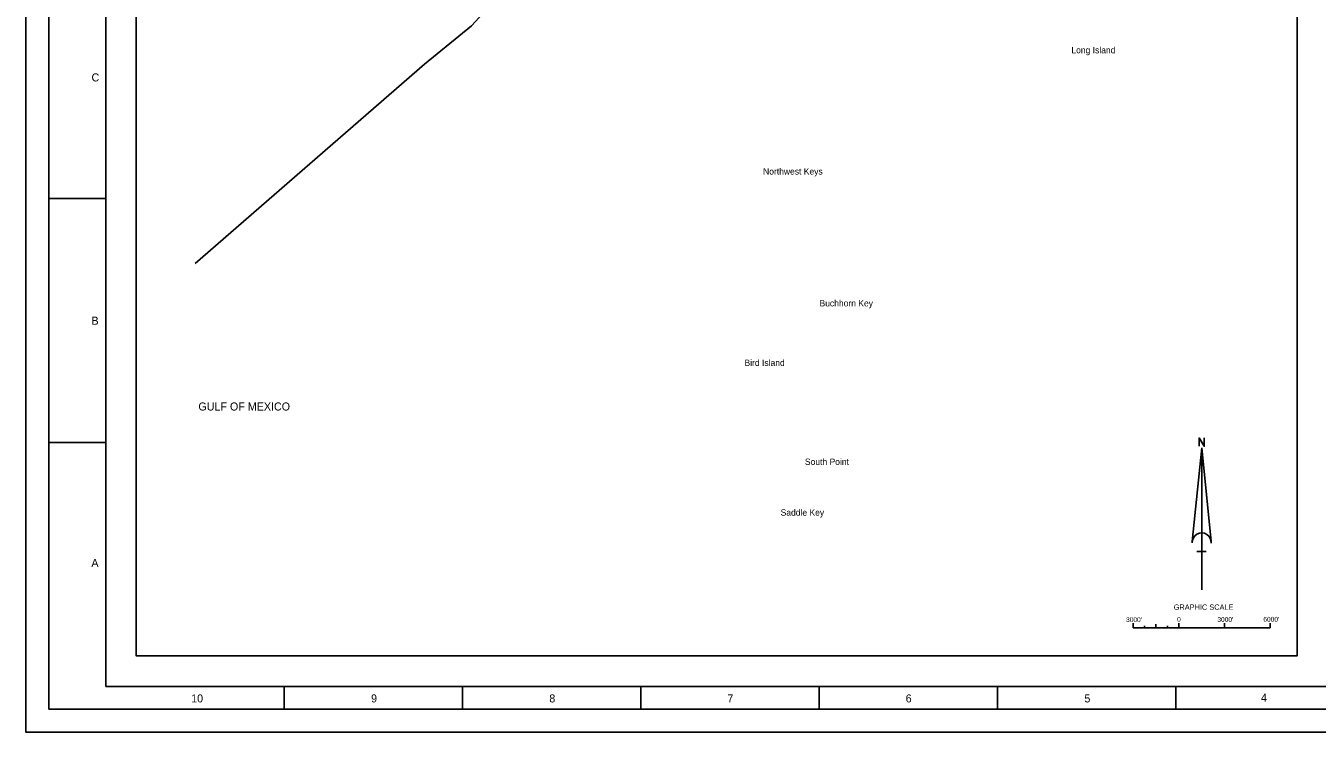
# Model space of a CAD drawing. Extents: x 384865 to 516869, y 1553900 to 1655899.
# Drawn here: x 384865 to 469592, y 1553900 to 1600221 of the extents above; entities that cross this region are included whole.
import ezdxf

# ---------------------------------------------------------------- set-up
doc = ezdxf.new("R2010")
doc.units = 0
for name, color, linetype in [('G-ANNO-NPLT', 7, 'Continuous'), ('G-ANNO-TTLB', 7, 'Continuous'), ('V-ANNO-NOTE', 7, 'Continuous'), ('V-ANNO-SYMB', 7, 'Continuous'), ('V-CHAN-CNTR', 7, 'Continuous'), ('V-SITE-IDEN', 7, 'Continuous'), ('V-SITE-WATR', 7, 'Continuous')]:
    doc.layers.add(name, color=color, linetype=linetype)

msp = doc.modelspace()

# ---------------------------------------------------------------- linework, layer by layer
at = {"layer": 'G-ANNO-NPLT'}
msp.add_lwpolyline([(384865, 1655899), (516865, 1655899), (516865, 1553900), (384865, 1553900)], close=True, dxfattribs=at)
msp.add_lwpolyline([(384865, 1555400), (384865, 1553900), (386365, 1553900)], dxfattribs=at)
at = {"layer": 'G-ANNO-TTLB'}
for p, q in [((386365, 1588898), (390115, 1588898)), ((386365, 1572899), (390115, 1572899)), ((401815, 1555400), (401815, 1556900)), ((413515, 1555400), (413515, 1556900)), ((425215, 1555400), (425215, 1556900)), ((436915, 1555400), (436915, 1556900)), ((448615, 1555400), (448615, 1556900)), ((460315, 1555400), (460315, 1556900))]:
    msp.add_line(p, q, dxfattribs=at)
for points in [[(386365, 1555400), (515365, 1555400), (515365, 1654399), (386365, 1654399)], [(513865, 1652899), (390115, 1652899), (390115, 1556900), (513865, 1556900)]]:
    msp.add_lwpolyline(points, close=True, dxfattribs=at)
at = {"layer": 'V-ANNO-NOTE'}
for p, q in [((457516, 1560738), (457516, 1561051)), ((457516, 1560738), (466516, 1560738)), ((458266, 1560738), (458266, 1560882)), ((459016, 1560738), (459016, 1560993)), ((459766, 1560738), (459766, 1560882)), ((460516, 1560738), (460516, 1561051)), ((460516, 1560738), (460516, 1561051)), ((460516, 1560738), (460516, 1560888)), ((463516, 1560738), (463516, 1561051)), ((466516, 1560738), (466516, 1561051))]:
    msp.add_line(p, q, dxfattribs=at)
at = {"layer": 'V-ANNO-SYMB'}
for p, q in [((461398, 1566407), (462016, 1572550)), ((462016, 1563242), (462016, 1572550)), ((462633, 1566407), (462016, 1572550)), ((462310, 1565756), (461689, 1565756))]:
    msp.add_line(p, q, dxfattribs=at)
msp.add_lwpolyline([(392115, 1650899), (468272, 1650899), (468272, 1558900), (392115, 1558900)], close=True, dxfattribs=at)
msp.add_lwpolyline([(461844, 1572650), (461844, 1573193), (462182, 1572650), (462182, 1573193)], dxfattribs=at)
msp.add_arc((462016, 1566345), 621, 355.29842, 182.06726, dxfattribs=at)
at = {"layer": 'V-CHAN-CNTR'}
for p, q in [((414111, 1600221), (416388, 1602708)), ((411013, 1597699), (414111, 1600221)), ((395987, 1584639), (411013, 1597699))]:
    msp.add_line(p, q, dxfattribs=at)

# ---------------------------------------------------------------- texts
at = {"layer": 'G-ANNO-TTLB'}
for s, p in [('C', (389177, 1596576)), ('B', (389172, 1580621)), ('A', (389167, 1564736)), ('10', (395714, 1555850)), ('9', (407518, 1555850)), ('8', (419213, 1555850)), ('7', (430896, 1555850)), ('6', (442595, 1555850)), ('5', (454320, 1555850)), ('4', (465905, 1555900))]:
    msp.add_text(s, height=525, dxfattribs=at).set_placement(p)
at = {"layer": 'V-ANNO-NOTE'}
for s, height, p in [('GRAPHIC SCALE', 349.99, (460180, 1561923)), ("3000'", 312.5, (457055, 1561120)), ('0', 312, (460405, 1561140)), ("3000'", 312.5, (463045, 1561131)), ("6000'", 312.5, (466062, 1561147))]:
    msp.add_text(s, height=height, dxfattribs=at).set_placement(p)
at = {"layer": 'V-SITE-IDEN'}
for s, p in [('Long Island', (453466, 1598420)), ('Northwest Keys', (433238, 1590467)), ('Buchhorn Key', (436941, 1581820)), ('Bird Island', (432019, 1577918)), ('South Point', (435984, 1571425)), ('Saddle Key', (434389, 1568097))]:
    msp.add_text(s, height=417.6, dxfattribs=at).set_placement(p)
at = {"layer": 'V-SITE-WATR'}
msp.add_text('GULF OF MEXICO', height=525.6, dxfattribs=at).set_placement((396189, 1574994))

doc.saveas('drawing.dxf')
